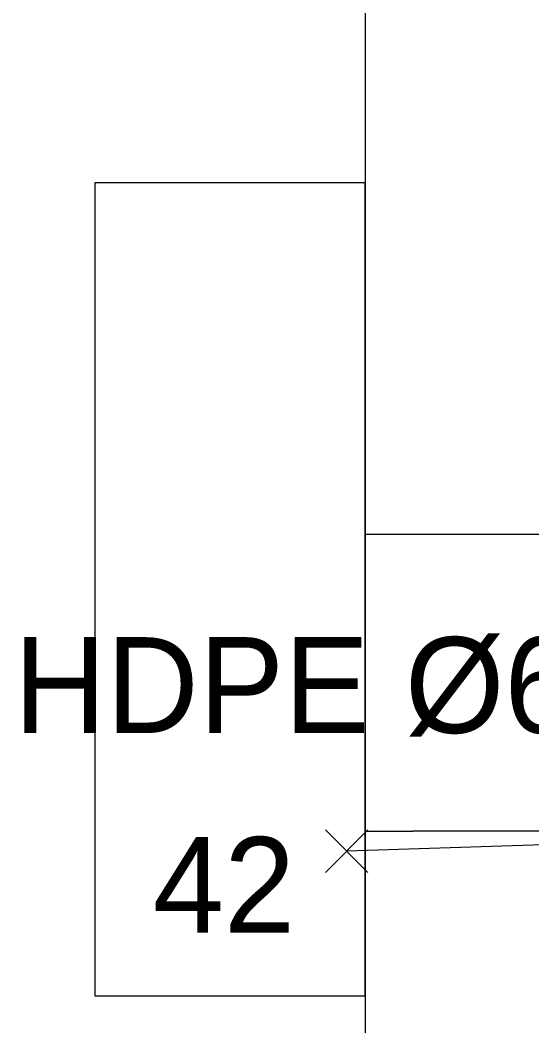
# Model space of a CAD drawing. Extents: x -263964 to -263544, y -1242317 to -1242020.
# Drawn here: x -263808.81 to -263798.11, y -1242184 to -1242163 of the extents above; entities that cross this region are included whole.
import ezdxf

# ---------------------------------------------------------------- set-up
doc = ezdxf.new("R2010")
doc.units = 0
for name, color, linetype in [('KFA_KOORDINACNA_SITUACIA_DSP_SEDA', 7, 'Continuous'), ('KFA_SO_50-1-II_BODY', 7, 'Continuous'), ('KFA_SO_50-1-II_VODOVODNE_PRIPOJKY', 7, 'Continuous'), ('POPIS', 7, 'Continuous')]:
    doc.layers.add(name, color=color, linetype=linetype)

msp = doc.modelspace()

# ---------------------------------------------------------------- linework, layer by layer
at = {"layer": 'KFA_KOORDINACNA_SITUACIA_DSP_SEDA'}
for p, q in [((-263807.243, -1242166.394), (-263807.243, -1242183.369)), ((-263801.593, -1242166.394), (-263807.243, -1242166.394)), ((-263801.593, -1242183.369), (-263801.593, -1242166.394)), ((-263801.593, -1242173.732), (-263800.593, -1242173.732)), ((-263800.593, -1242173.732), (-263793.257, -1242173.732)), ((-263801.593, -1242179.932), (-263800.593, -1242179.932)), ((-263788.893, -1242179.932), (-263800.593, -1242179.932)), ((-263807.243, -1242183.369), (-263801.593, -1242183.369))]:
    msp.add_line(p, q, dxfattribs=at)
msp.add_lwpolyline([(-263909.043, -1242125.432), (-263902.343, -1242125.432), (-263902.343, -1242104.482), (-263902.112, -1242103.927), (-263898.54, -1242100.355), (-263895.995, -1242097.81), (-263892.423, -1242094.238), (-263891.868, -1242094.007), (-263812.071, -1242094.007), (-263811.513, -1242094.238), (-263801.823, -1242103.927), (-263801.593, -1242104.482), (-263801.593, -1242224.282), (-263801.824, -1242224.838), (-263805.392, -1242228.407)], dxfattribs=at)
msp.add_lwpolyline([(-263801.593, -1242166.394), (-263807.243, -1242166.394), (-263807.243, -1242183.369), (-263801.593, -1242183.369)], close=True, dxfattribs=at)
at = {"layer": 'KFA_SO_50-1-II_BODY'}
for p, q in [((-263802.418, -1242180.791), (-263801.534, -1242179.907)), ((-263801.534, -1242180.791), (-263802.418, -1242179.907))]:
    msp.add_line(p, q, dxfattribs=at)
at = {"layer": 'KFA_SO_50-1-II_VODOVODNE_PRIPOJKY'}
msp.add_lwpolyline([(-263788.092, -1242179.915), (-263788.356, -1242179.911), (-263801.976, -1242180.349)], dxfattribs=at)

# ---------------------------------------------------------------- texts
at = {"layer": 'KFA_SO_50-1-II_BODY'}
msp.add_text('42', height=2, dxfattribs=at).set_placement((-263806.03, -1242182.054))
at = {"layer": 'POPIS'}
msp.add_text('HDPE Ø63mm - 13,89m', height=2, dxfattribs=at).set_placement((-263808.935, -1242177.88))

doc.saveas('drawing.dxf')
